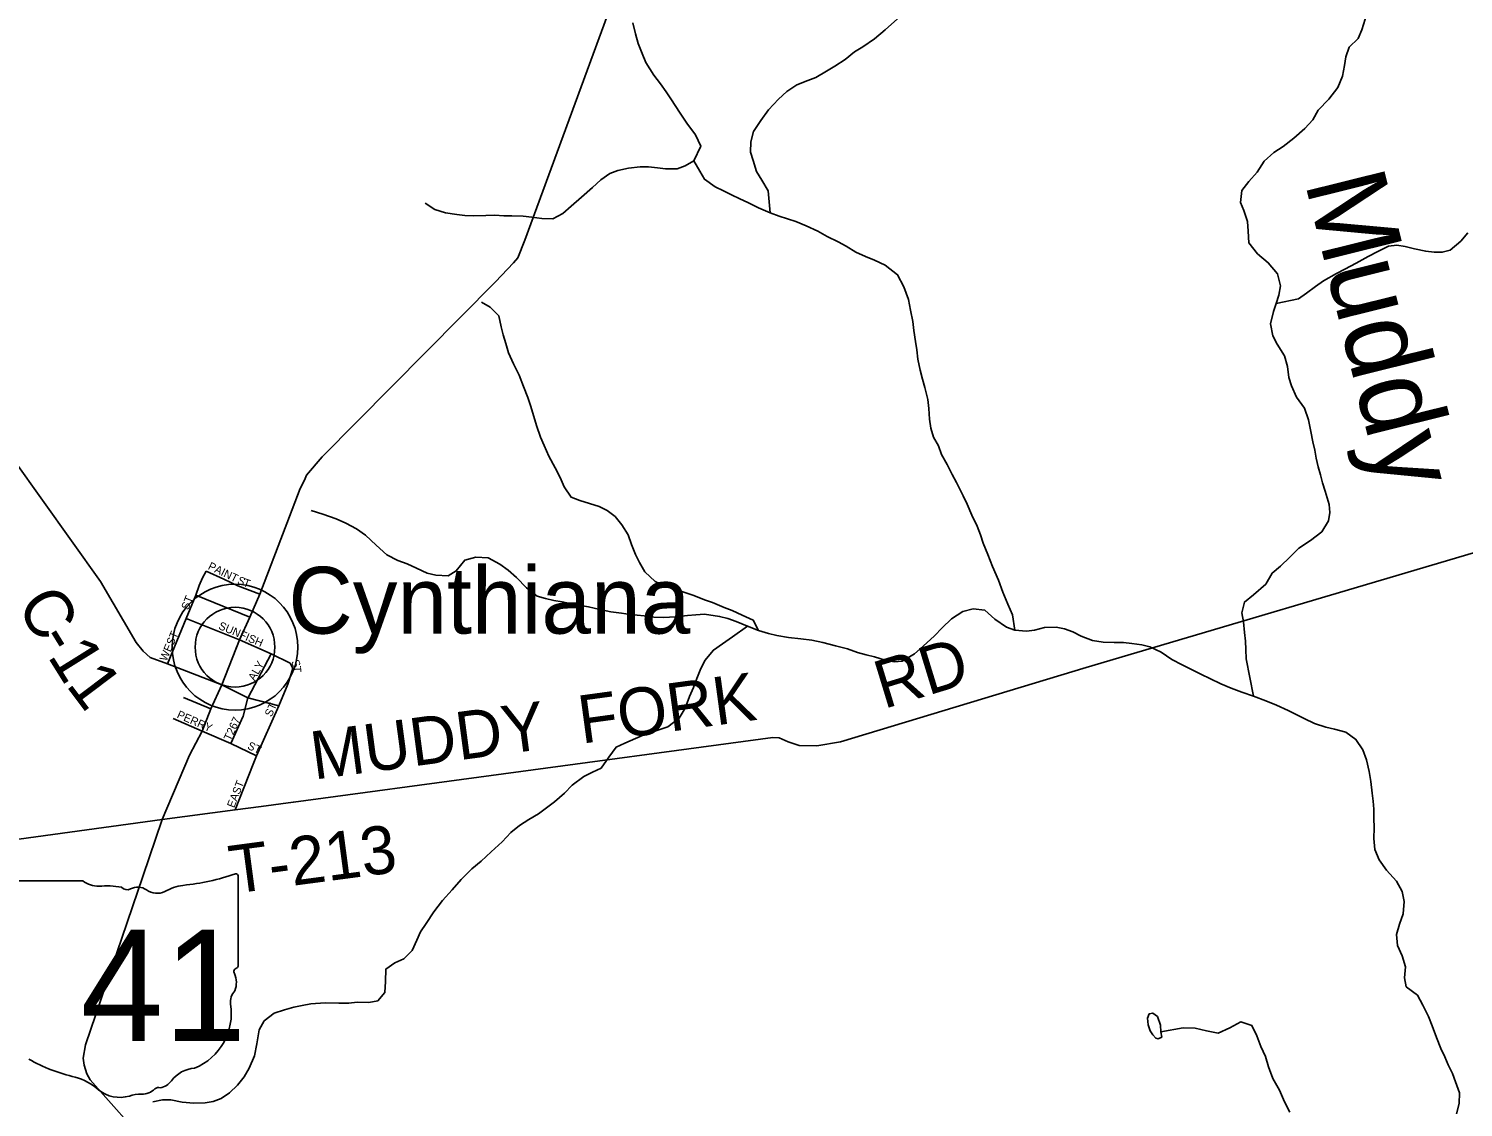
# Model space of a CAD drawing. Extents: x 1578669 to 1989827, y 208020 to 553079.
# Drawn here: x 1726783 to 1735744, y 426002 to 432739 of the extents above; entities that cross this region are included whole.
import ezdxf

# ---------------------------------------------------------------- set-up
doc = ezdxf.new("R2010")
doc.units = 0
for name, color, linetype in [('GM_X_County_Road', 7, 'Continuous'), ('GM_X_County_Road_Text', 7, 'Continuous'), ('GM_X_Minor_Lake', 7, 'Continuous'), ('GM_X_Minor_River', 7, 'Continuous'), ('GM_X_Minor_River_Text', 7, 'Continuous'), ('GM_X_State_Location', 7, 'Continuous'), ('GM_X_State_Route', 7, 'Continuous'), ('GM_X_State_Shield', 7, 'Continuous'), ('GM_X_Township_Road', 7, 'Continuous'), ('GM_X_Township_Road_Text', 7, 'Continuous'), ('GM_X_Township_Subdivision', 7, 'Continuous'), ('GM_X_Township_Subdivision_Text', 7, 'Continuous'), ('GM_X_Unincorporated', 7, 'Continuous'), ('GM_X_Unincorporated_Location', 7, 'Continuous'), ('GM_X_Unincorporated_Text', 7, 'Continuous')]:
    doc.layers.add(name, color=color, linetype=linetype)

msp = doc.modelspace()

# ---------------------------------------------------------------- linework, layer by layer
at = {"layer": 'GM_X_County_Road'}
msp.add_lwpolyline([(1727990.2, 428639.8), (1727649.4, 428771.8), (1727542.9, 428812.3), (1727498.1, 428850.7), (1727455.5, 428906.1), (1727231.8, 429285.2), (1726688.4, 430049), (1726260.4, 430732.5), (1726238.5, 430777.7), (1726208.9, 430869.6), (1726010.6, 431725.9), (1725743.5, 432717.6)], dxfattribs=at)
at = {"layer": 'GM_X_Minor_Lake'}
for points in [[(1733854.7, 426474.5), (1733852.7, 426514.6), (1733834.7, 426568.7), (1733804.6, 426590.7), (1733782.6, 426586.7), (1733772.5, 426558.6), (1733776.5, 426516.5), (1733788.5, 426480.4), (1733804.6, 426454.3), (1733824.6, 426434.3), (1733838.6, 426430.3), (1733860.7, 426440.4)], [(1733860.7, 426440.4), (1733854.7, 426474.5)]]:
    msp.add_lwpolyline(points, dxfattribs=at)
at = {"layer": 'GM_X_Minor_River'}
for points in [[(1734434.6, 428569.8), (1734388.6, 428802.5), (1734386.6, 428860.6), (1734384.6, 428912.8), (1734376.6, 428967), (1734370.7, 429035.2), (1734360.7, 429091.3), (1734376.7, 429157.6), (1734432.9, 429201.8), (1734511, 429270.1), (1734551.2, 429338.4), (1734601.3, 429382.6), (1734661.4, 429438.9), (1734717.5, 429495.2), (1734789.7, 429541.4), (1734859.9, 429595.7), (1734902, 429666), (1734910, 429716.2), (1734906, 429766.3), (1734882, 429850.6), (1734864, 429902.7), (1734852, 429952.8), (1734838, 430003), (1734826, 430057.1), (1734816.1, 430107.3), (1734804.1, 430159.4), (1734792.1, 430223.6), (1734778.1, 430295.9), (1734752.1, 430368.1), (1734702.1, 430438.2), (1734670, 430508.4), (1734654.1, 430560.6), (1734646.1, 430628.8), (1734628.1, 430695), (1734582.1, 430769.2), (1734554, 430821.3), (1734540.1, 430895.5), (1734558.1, 430971.8), (1734576.2, 431022), (1734592.3, 431074.2), (1734602.3, 431132.4), (1734584.4, 431206.6), (1734526.3, 431276.8), (1734458.2, 431332.9), (1734404.2, 431401.1), (1734400.2, 431473.3), (1734396.3, 431533.5), (1734374.3, 431603.7), (1734352.3, 431653.9), (1734360.4, 431728.1), (1734404.5, 431784.4), (1734456.6, 431842.6), (1734500.7, 431910.9), (1734560.9, 431965.2), (1734619, 432003.4), (1734685.2, 432055.7), (1734755.3, 432116), (1734803.4, 432170.2), (1734837.6, 432230.5), (1734903.7, 432298.8), (1734959.9, 432371.1), (1734990, 432441.4), (1735002, 432509.6), (1735010.1, 432563.8), (1735030.2, 432624), (1735088.3, 432676.3), (1735110.4, 432730.5), (1735142.5, 432830.9)], [(1730938.5, 431914.2), (1730980.7, 432004.6), (1730948.7, 432074.8), (1730894.7, 432149), (1730848.7, 432217.2), (1730798.7, 432293.5), (1730764.7, 432343.6), (1730728.7, 432393.8), (1730688.7, 432447.9), (1730638.7, 432528.1), (1730614.7, 432584.3), (1730590.8, 432646.5), (1730572.8, 432706.7), (1730556.9, 432775)], [(1731415.1, 431587.7), (1731403.2, 431726.2), (1731363.2, 431792.3), (1731329.2, 431846.5), (1731309.2, 431914.7), (1731291.2, 431966.9), (1731293.3, 432031.1), (1731311.4, 432097.4), (1731355.6, 432165.7), (1731403.7, 432232), (1731465.9, 432298.4), (1731518.1, 432346.6), (1731582.2, 432388.9), (1731650.4, 432415.1), (1731700.5, 432433.2), (1731766.6, 432473.4), (1731818.7, 432503.6), (1731882.9, 432545.9), (1731941.1, 432594.1), (1731993.2, 432626.3), (1732065.4, 432674.6), (1732133.5, 432730.9), (1732209.7, 432799.2)], [(1732943.9, 428982.9), (1732927.9, 429077.2), (1732899.9, 429145.3), (1732867.9, 429219.5), (1732839.9, 429293.7), (1732803.9, 429380), (1732773.9, 429454.2), (1732745.9, 429526.4), (1732727.9, 429578.5), (1732707.9, 429630.7), (1732673.8, 429700.8), (1732645.8, 429769), (1732619.8, 429821.2), (1732577.8, 429903.4), (1732551.8, 429953.5), (1732519.8, 430017.7), (1732485.7, 430079.9), (1732465.7, 430134), (1732435.7, 430188.2), (1732417.7, 430244.3), (1732409.8, 430300.5), (1732405.8, 430366.7), (1732399.8, 430422.9), (1732379.8, 430497.1), (1732365.9, 430549.3), (1732351.9, 430605.5), (1732337.9, 430673.7), (1732329.9, 430731.9), (1732322, 430784.1), (1732312, 430854.3), (1732306.1, 430910.5), (1732292.1, 430980.7), (1732278.1, 431046.9), (1732250.1, 431127.2), (1732210.1, 431201.4), (1732132, 431261.5), (1732066, 431293.5), (1732009.9, 431315.5), (1731949.8, 431343.5), (1731889.7, 431379.6), (1731839.7, 431407.6), (1731771.6, 431441.6), (1731711.5, 431473.7), (1731639.4, 431507.7), (1731575.3, 431533.7), (1731523.2, 431551.7), (1731471.1, 431567.7), (1731415.1, 431587.7), (1731341, 431619.7), (1731274.9, 431653.7), (1731224.8, 431675.7), (1731172.7, 431701.8), (1731122.7, 431725.8), (1731070.6, 431751.8), (1731004.5, 431797.9), (1730974.5, 431848), (1730938.5, 431914.2), (1730884.4, 431882), (1730834.3, 431863.9), (1730760.2, 431863.8), (1730710.1, 431869.7), (1730654, 431875.7), (1730601.9, 431875.6), (1730529.7, 431867.5), (1730463.6, 431853.3), (1730413.5, 431833.2), (1730357.3, 431795), (1730305.2, 431746.7), (1730237, 431686.4), (1730170.8, 431630.1), (1730118.7, 431583.8), (1730056.5, 431551.6), (1729988.4, 431553.5), (1729926.3, 431561.5), (1729872.2, 431567.4), (1729802.1, 431569.3), (1729752, 431569.2), (1729695.9, 431573.1), (1729637.8, 431571.1), (1729559.6, 431568.9), (1729507.5, 431572.9), (1729457.4, 431578.8), (1729387.3, 431588.8), (1729319.2, 431608.8), (1729259.1, 431648.8)], [(1734576.2, 431022), (1734714.5, 431052.3), (1734764.6, 431086.5), (1734820.7, 431128.7), (1734870.8, 431162.9), (1734953, 431209.1), (1735005.1, 431237.3), (1735075.3, 431273.5), (1735149.4, 431315.7), (1735209.5, 431347.9), (1735277.7, 431380.1), (1735329.8, 431386.2), (1735381.9, 431378.2), (1735439.9, 431364.3), (1735510, 431348.3), (1735562.1, 431342.4), (1735612.2, 431342.4), (1735662.3, 431354.5), (1735728.5, 431410.8), (1735772.6, 431463)], [(1731340.8, 428980.4), (1731308.8, 429044.6), (1731240.7, 429076.6), (1731176.5, 429104.6), (1731126.5, 429124.6), (1731054.3, 429154.6), (1731004.2, 429172.5), (1730938.1, 429198.5), (1730876, 429220.5), (1730817.9, 429238.5), (1730749.8, 429260.5), (1730695.7, 429286.5), (1730631.6, 429346.6), (1730597.6, 429404.7), (1730573.6, 429454.8), (1730549.6, 429517), (1730527.6, 429577.2), (1730487.6, 429639.3), (1730447.5, 429691.5), (1730397.5, 429729.5), (1730347.4, 429753.5), (1730285.3, 429773.5), (1730225.2, 429791.5), (1730171.1, 429813.5), (1730127, 429877.6), (1730103, 429935.8), (1730071, 429995.9), (1730033, 430068.1), (1730003, 430136.3), (1729981, 430188.5), (1729955, 430260.7), (1729939, 430316.9), (1729917.1, 430385.1), (1729901.1, 430435.2), (1729873.1, 430503.5), (1729847.1, 430575.7), (1729811.1, 430645.9), (1729781.1, 430714.1), (1729763.1, 430772.3), (1729747.2, 430826.4), (1729735.2, 430876.6), (1729719.2, 430944.8), (1729665.2, 430999), (1729611.1, 431031)], [(1734053.9, 428731.7), (1733987.8, 428765.8), (1733923.7, 428799.8), (1733857.6, 428843.8), (1733785.5, 428877.8), (1733735.4, 428889.8), (1733673.3, 428899.7), (1733621.2, 428905.7), (1733563.1, 428905.6), (1733494.9, 428907.5), (1733428.8, 428917.4), (1733356.7, 428945.4), (1733304.6, 428971.4), (1733252.5, 428991.4), (1733200.4, 429001.3), (1733128.3, 428999.2), (1733066.1, 428983.1), (1733016, 428975), (1732943.9, 428982.9), (1732891.8, 429000.9), (1732817.7, 429050.9), (1732755.6, 429107), (1732683.5, 429114.9), (1732617.3, 429098.8), (1732547.2, 429052.5), (1732489, 428996.2), (1732440.9, 428946), (1732370.7, 428881.7), (1732316.6, 428833.4), (1732238.4, 428789.2), (1732188.3, 428785.1), (1732132.2, 428795), (1732066.1, 428815), (1732014, 428829), (1731959.9, 428842.9), (1731897.8, 428864.9), (1731823.7, 428884.9), (1731743.5, 428904.8), (1731675.4, 428918.7), (1731605.3, 428928.7), (1731529.1, 428936.6), (1731457, 428948.5), (1731404.9, 428960.5), (1731340.8, 428980.4), (1731272.7, 429006.4), (1731202.5, 429036.4), (1731150.5, 429054.4), (1731098.4, 429068.3), (1731004.2, 429082.2), (1730950.1, 429078.1), (1730898, 429074.1), (1730823.8, 429065.9), (1730747.7, 429061.8), (1730687.5, 429063.7), (1730627.4, 429071.6), (1730539.3, 429079.5), (1730485.2, 429087.5), (1730419, 429097.4), (1730350.9, 429111.3), (1730280.8, 429127.3), (1730230.7, 429137.2), (1730174.6, 429147.2), (1730114.5, 429159.1), (1730064.4, 429167.1), (1730012.3, 429179), (1729960.2, 429195), (1729892.1, 429247.1), (1729830, 429311.2), (1729778, 429357.3), (1729725.9, 429395.3), (1729653.8, 429433.3), (1729575.6, 429437.2), (1729507.5, 429419.1), (1729453.3, 429352.8), (1729403.2, 429320.6), (1729327, 429326.5), (1729272.9, 429338.4), (1729204.8, 429368.4), (1729146.7, 429396.4), (1729088.6, 429416.4), (1729020.5, 429452.4), (1728954.4, 429512.5), (1728886.4, 429574.6), (1728830.3, 429614.7), (1728764.2, 429650.7), (1728704.1, 429676.7), (1728619.9, 429706.7), (1728547.8, 429728.7)], [(1731272.7, 429006.4), (1731180.4, 428940), (1731116.3, 428897.8), (1731060.2, 428857.6), (1731006, 428793.3), (1730977.9, 428733), (1730955.9, 428680.8), (1730935.8, 428624.6), (1730911.7, 428568.4), (1730883.6, 428494.1), (1730845.5, 428431.9), (1730775.3, 428377.6), (1730707.2, 428355.4), (1730637, 428333.2), (1730572.9, 428305), (1730506.7, 428276.8), (1730452.6, 428250.6), (1730406.5, 428188.4), (1730358.4, 428120.1), (1730304.2, 428095.9), (1730250.1, 428067.7), (1730177.9, 428013.5), (1730129.8, 427963.2), (1730067.7, 427911), (1729967.4, 427834.5), (1729907.3, 427800.3), (1729849.2, 427762.1), (1729795, 427717.9), (1729740.9, 427659.6), (1729672.7, 427597.3), (1729608.6, 427539), (1729550.5, 427490.8), (1729484.3, 427424.5), (1729428.1, 427360.2), (1729368, 427293.9), (1729313.9, 427223.6), (1729265.7, 427149.3), (1729229.7, 427099.1), (1729207.6, 427046.9), (1729179.5, 426980.6), (1729127.4, 426930.4), (1729071.3, 426904.2), (1729015.1, 426866), (1729011.1, 426787.8), (1729007.1, 426719.5), (1728965, 426667.3), (1728908.9, 426657.2), (1728834.7, 426659.1), (1728782.6, 426653), (1728720.5, 426652.9), (1728634.3, 426654.8), (1728546.1, 426648.6), (1728492, 426638.5), (1728439.9, 426628.4), (1728381.8, 426610.2), (1728315.7, 426590.1), (1728253.5, 426541.8), (1728223.4, 426485.6), (1728207.4, 426399.3), (1728193.3, 426323.1), (1728161.3, 426246.8), (1728129.2, 426192.6), (1728087.1, 426140.3), (1728037, 426092.1), (1727984.9, 426058), (1727934.8, 426037.8), (1727884.7, 426029.7), (1727814.5, 426027.6), (1727742.4, 426033.5), (1727670.2, 426049.4), (1727620.1, 426049.3), (1727558, 426037.2)], [(1735702.2, 425961.8), (1735718.2, 426026), (1735720.3, 426092.2), (1735696.2, 426160.4), (1735676.2, 426212.5), (1735650.1, 426266.6), (1735628.1, 426316.8), (1735604.1, 426368.9), (1735576, 426439), (1735550, 426511.2), (1735526, 426569.3), (1735491.9, 426639.5), (1735457.9, 426701.6), (1735387.8, 426755.7), (1735377.7, 426811.8), (1735383.8, 426880), (1735361.8, 426948.2), (1735333.7, 427012.4), (1735327.7, 427080.6), (1735345.8, 427146.8), (1735367.8, 427211), (1735373.9, 427287.3), (1735361.9, 427349.4), (1735327.8, 427415.6), (1735263.7, 427483.7), (1735217.7, 427547.8), (1735191.6, 427612), (1735185.6, 427680.2), (1735187.7, 427748.4), (1735185.7, 427808.6), (1735185.7, 427864.7), (1735181.7, 427914.9), (1735175.7, 427965), (1735165.7, 428037.2), (1735155.7, 428099.4), (1735139.7, 428171.6), (1735115.7, 428235.8), (1735073.7, 428299.9), (1735009.5, 428346), (1734939.4, 428363.9), (1734885.3, 428375.9), (1734815.2, 428399.8), (1734751.1, 428429.8), (1734701, 428455.8), (1734650.9, 428479.8), (1734576.8, 428513.8), (1734510.7, 428539.8), (1734434.6, 428569.8), (1734360.4, 428595.8), (1734294.3, 428619.8), (1734230.2, 428647.7), (1734160.1, 428679.7), (1734108, 428705.8), (1734053.9, 428731.7)], [(1734660.2, 425972.2), (1734628.1, 426036.4), (1734596.1, 426108.5), (1734554, 426182.7), (1734528, 426254.8), (1734507.9, 426319), (1734479.9, 426381.1), (1734453.9, 426449.3), (1734423.8, 426513.5), (1734353.7, 426535.4), (1734285.5, 426499.2), (1734213.4, 426465), (1734139.2, 426480.9), (1734069.1, 426496.9), (1733995, 426498.8), (1733854.7, 426474.5)]]:
    msp.add_lwpolyline(points, dxfattribs=at)
at = {"layer": 'GM_X_State_Route'}
for points in [[(1728413, 429692.9), (1728479.9, 429867.4), (1728505.5, 429919), (1728518.4, 429950.7), (1728616, 430064.7), (1729699.1, 431156.9), (1729810.9, 431276.4), (1729837.9, 431307.9), (1729883.2, 431417.2), (1730825.1, 433986), (1730837.9, 434011.8), (1730867, 434047.2), (1731788.6, 434767.9), (1731819.4, 434791.2), (1731884.6, 434825.6), (1733351, 435603.6), (1733387.6, 435620.7), (1733508.8, 435653.6), (1734375.9, 435920.2), (1735416.9, 436289), (1735824.5, 436420.2)], [(1727496.9, 427444.6), (1727618.1, 427800.3), (1727787.8, 428200.7), (1727867.7, 428352.2), (1727920.8, 428490.3), (1727990.2, 428639.8), (1728101, 428921), (1728164, 429064.1), (1728226.6, 429206.4), (1728413, 429692.9)], [(1727543.4, 425749.8), (1727168.2, 426173.2), (1727147.2, 426211.9), (1727130.6, 426266.4), (1727123.9, 426308.9), (1727138.3, 426392.8), (1727496.9, 427444.6)]]:
    msp.add_lwpolyline(points, dxfattribs=at)
at = {"layer": 'GM_X_State_Shield'}
for p, q in [((1728092.7, 426890), (1728092.7, 427442.8)), ((1727121.9, 427416.6), (1726714.2, 427416.6)), ((1728092.6, 426890.2), (1728092.7, 426890))]:
    msp.add_line(p, q, dxfattribs=at)
for centre, radius, start, end in [((1727596.8, 428857.1), 1476.4, 275.84447, 288.90645), ((1728077.3, 427445.1), 15.5, 351.86209, 97.738), ((1727219, 427539.3), 156.4, 231.61951, 271.11188), ((1727270.9, 426823.4), 561.6, 80.48669, 94.98827), ((1727398.4, 427406.1), 45.1, 219.79206, 297.10237), ((1727464.7, 427284), 93.8, 54.46668, 119.14113), ((1727585.8, 427451.5), 112.9, 233.85621, 294.82819), ((1727785.1, 427093.9), 297, 97.34618, 120.76885), ((1728089.1, 426849.5), 24, 107.94398, 210.33697), ((1727936.5, 426779.6), 144, 340.03296, 23.64957), ((1728076.2, 426887.9), 16.6, 289.60381, 7.73413), ((1728148.2, 426658.7), 104.8, 136.8065, 186.92959), ((1727679.5, 426588.4), 369.3, 292.30889, 8.98584), ((1727309.8, 427230.2), 1066.1, 240.41292, 257.1985), ((1726991.9, 425867.1), 333.6, 47.18416, 75.83597), ((1727835.2, 426045.1), 202.2, 94.40312, 142.57675), ((1727352.7, 426275.6), 211.7, 230.70037, 286.29184), ((1727490.5, 426196.4), 112.8, 268.77702, 315.54927), ((1727592.5, 426094.1), 31.8, 65.75173, 132.64842), ((1727579, 426239.4), 119.3, 282.87319, 323.27711), ((1727475, 425910.3), 173.9, 85.69512, 111.20995)]:
    msp.add_arc(centre, radius, start, end, dxfattribs=at)
at = {"layer": 'GM_X_Township_Road'}
for points in [[(1728437, 427907.8), (1729671.2, 428075.1), (1731431.1, 428312.6), (1731471, 428308.8), (1731528, 428284), (1731595.1, 428262.8), (1731705.3, 428259.7), (1731854.8, 428284.9), (1733389, 428749.9), (1735864, 429482.4), (1738440, 430235.9)], [(1727618.1, 427800.3), (1728072.2, 427859.3), (1728236.2, 427880.6), (1728436.1, 427907.7), (1728437, 427907.8)], [(1726248.3, 427611.5), (1727618.1, 427800.3)]]:
    msp.add_lwpolyline(points, dxfattribs=at)
at = {"layer": 'GM_X_Township_Subdivision'}
for points in [[(1727649.4, 428771.8), (1727766.5, 429055.2), (1727828.3, 429200), (1727847.5, 429261.3), (1727868.8, 429308.7), (1727892.2, 429351.3)], [(1727892.2, 429351.3), (1728003, 429300.2), (1728090.3, 429259.7), (1728226.6, 429206.4)], [(1727828.3, 429200), (1728164, 429064.1)], [(1727766.5, 429055.2), (1728101, 428921), (1728296.9, 428833.6), (1728416.2, 428776.1), (1728433.3, 428744.2), (1728422.6, 428710.1)], [(1728153.3, 428561.2), (1728296.9, 428833.6)], [(1728186, 428144.3), (1728207.2, 428197.6), (1728345.9, 428509.8), (1728401.3, 428644.1), (1728422.6, 428710.1)], [(1727990.2, 428639.8), (1728152.1, 428558.9), (1728161.3, 428556.5)], [(1727749.5, 428561), (1727920.8, 428490.3)], [(1728046.6, 428273.4), (1728122.3, 428444.9), (1728152.1, 428558.9), (1728153.3, 428561.2)], [(1728161.3, 428556.5), (1728345.9, 428509.8)], [(1727686.6, 428430), (1727867.7, 428352.2), (1728046.6, 428273.4), (1728207.2, 428197.6)], [(1728072.2, 427859.3), (1728186, 428144.3)]]:
    msp.add_lwpolyline(points, dxfattribs=at)
at = {"layer": 'GM_X_Unincorporated'}
for radius in [392.8, 249]:
    msp.add_circle((1728072, 428876), radius, dxfattribs=at)
at = {"layer": 'GM_X_Unincorporated_Location'}
msp.add_line((1728072, 428876), (1728072, 428876), dxfattribs=at)

# ---------------------------------------------------------------- texts
at = {"layer": 'GM_X_County_Road_Text'}
for s, rotation, p in [('C', 301.55816, (1726702.5, 429136.8)), ('-', 301.64038, (1726831.7, 428926.5)), ('1', 301.96685, (1726897.3, 428820)), ('1', 306.99196, (1727011.4, 428639.6))]:
    msp.add_text(s, height=300, rotation=rotation, dxfattribs=at).set_placement(p)
at = {"layer": 'GM_X_Minor_River_Text'}
msp.add_text('Muddy', height=500.26, rotation=283.93683, dxfattribs=at).set_placement((1734753.1, 431780.3))
at = {"layer": 'GM_X_State_Location'}
msp.add_text('41', height=1, rotation=0.00001, dxfattribs=at).set_placement((1727129.1, 426727.1))
for s in ['s', 'r']:
    msp.add_text(s, height=1, dxfattribs=at).set_placement((1727380.9, 426799.8))
at = {"layer": 'GM_X_State_Shield'}
msp.add_text('41', height=696.1, dxfattribs=at).set_placement((1727107.8, 426416.3))
at = {"layer": 'GM_X_Township_Road_Text'}
for s, rotation, p in [('RD', 17.03033, (1732123.7, 428488.5)), ('FORK', 7.76579, (1730237.1, 428272.7)), ('MUDDY', 7.61859, (1728565.6, 428048.3)), ('T-213', 7.57458, (1728056.7, 427335.4))]:
    msp.add_text(s, height=300, rotation=rotation, dxfattribs=at).set_placement(p)
at = {"layer": 'GM_X_Township_Subdivision_Text'}
for s, rotation, p in [('PAINT', 334.055, (1727898.8, 429365.2)), ('S', 335.64647, (1728082.2, 429275.6)), ('T', 340.08593, (1728118.2, 429259.5)), ('ST', 68.2011, (1727780.4, 429105.1)), ('WEST', 66.80215, (1727644.1, 428784.1)), ('SUNFISH', 336.92832, (1727964.6, 428991.4)), ('ALY', 60.74904, (1728194.6, 428661.8)), ('S', 291.86738, (1728421.9, 428785.6)), ('T', 274.21218, (1728434.1, 428756.9)), ('ST', 64.9823, (1728299.8, 428436.8)), ('PERRY', 336.30019, (1727704.9, 428437)), ('T267', 65.22059, (1728044.6, 428287.1)), ('ST', 334.98231, (1728145.1, 428243.3)), ('EAST', 68.49838, (1728066.4, 427868.6))]:
    msp.add_text(s, height=50, rotation=rotation, dxfattribs=at).set_placement(p)
at = {"layer": 'GM_X_Unincorporated_Text'}
msp.add_text('Cynthiana', height=417, rotation=0.00001, dxfattribs=at).set_placement((1728405.1, 428960.6))

doc.saveas('drawing.dxf')
